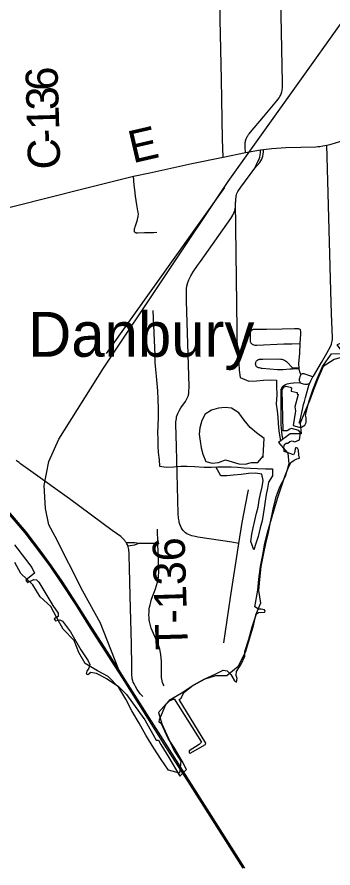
# Model space of a CAD drawing. Extents: x 63.4 to 97.4, y 0.4 to 22.4.
# Drawn here: x 69.147 to 69.704, y 14.543 to 16.043 of the extents above; entities that cross this region are included whole.
import ezdxf

# ---------------------------------------------------------------- set-up
doc = ezdxf.new("R2010")
doc.units = 0
for name, color, linetype in [('GM_X_County_Road', 7, 'Continuous'), ('GM_X_County_Road_Text', 7, 'Continuous'), ('GM_X_Major_Lake', 7, 'Continuous'), ('GM_X_Minor_River', 7, 'Continuous'), ('GM_X_Rail_Line', 7, 'Continuous'), ('GM_X_Township_Road', 7, 'Continuous'), ('GM_X_Township_Road_Text', 7, 'Continuous'), ('GM_X_Unincorporated_Text', 7, 'Continuous'), ('SH_Cut_Line', 7, 'Continuous')]:
    doc.layers.add(name, color=color, linetype=linetype)

msp = doc.modelspace()

# ---------------------------------------------------------------- linework, layer by layer
at = {"layer": 'GM_X_County_Road'}
for p, q in [((69.5103, 15.796), (69.5497, 15.8042)), ((69.5497, 15.8042), (69.5762, 15.8087))]:
    msp.add_line(p, q, dxfattribs=at)
for points in [[(69.6931, 15.8171), (69.701, 15.8189), (69.7158, 15.8236), (69.7305, 15.8292)], [(69.5762, 15.8087), (69.5773, 15.8089), (69.5814, 15.8094), (69.5959, 15.8112), (69.6208, 15.8125), (69.6737, 15.8141), (69.6773, 15.8144), (69.6806, 15.8148), (69.6859, 15.8155), (69.6931, 15.8171)], [(69.3521, 15.7622), (69.381, 15.7683), (69.4552, 15.7846), (69.5103, 15.796)], [(69.1254, 15.7052), (69.1419, 15.7092), (69.2655, 15.7405), (69.3521, 15.7622)], [(69.1423, 15.1125), (69.1618, 15.087), (69.1732, 15.0722), (69.1779, 15.0622), (69.1622, 15.0502), (69.1656, 15.0462), (69.1764, 15.051), (69.1813, 15.0506), (69.1856, 15.0467), (69.21, 15.0054), (69.2195, 14.9918), (69.2192, 14.9863), (69.2123, 14.9818), (69.2146, 14.9786), (69.2221, 14.9799), (69.2271, 14.9778), (69.2414, 14.9591), (69.2596, 14.9274), (69.2723, 14.908), (69.2755, 14.9014), (69.2734, 14.8949), (69.2699, 14.8896), (69.2689, 14.885), (69.2717, 14.8838), (69.2768, 14.8877), (69.2866, 14.8861), (69.3047, 14.8768), (69.3251, 14.8632), (69.34, 14.8484), (69.3503, 14.8341), (69.3721, 14.8041), (69.3921, 14.7678), (69.3965, 14.7681), (69.4005, 14.7603), (69.4148, 14.7376), (69.4341, 14.7044), (69.4456, 14.7166), (69.4378, 14.7308), (69.4239, 14.7549), (69.4132, 14.771), (69.4014, 14.7968), (69.3976, 14.7996), (69.3983, 14.8046), (69.4016, 14.8129), (69.4093, 14.8311), (69.4158, 14.8373), (69.4239, 14.8407), (69.4719, 14.7643), (69.4683, 14.7602), (69.4504, 14.749), (69.4504, 14.7461), (69.4523, 14.7452), (69.4793, 14.7607), (69.4798, 14.7626), (69.4327, 14.8395), (69.4361, 14.8419), (69.4413, 14.8522), (69.4576, 14.8649), (69.477, 14.8756), (69.4963, 14.8843), (69.5101, 14.8912), (69.5177, 14.8905), (69.5238, 14.8838), (69.5296, 14.8739), (69.5336, 14.8705), (69.535, 14.8769), (69.533, 14.8822), (69.5341, 14.8889), (69.5421, 14.9021), (69.5486, 14.916), (69.5487, 14.9242), (69.5555, 14.9459), (69.5616, 14.9676), (69.5694, 14.9907), (69.5726, 14.9933), (69.5833, 14.9935), (69.5844, 14.9949), (69.5833, 14.9978), (69.5776, 14.9992), (69.5726, 14.9988), (69.5664, 15.0031), (69.5714, 15.0322), (69.5733, 15.0516), (69.576, 15.0744), (69.5802, 15.0946), (69.584, 15.1151), (69.5885, 15.1341), (69.5998, 15.1721), (69.6064, 15.1938), (69.6189, 15.233), (69.625, 15.2478), (69.6298, 15.2576), (69.6356, 15.2614), (69.6402, 15.2639), (69.6452, 15.2654), (69.6439, 15.2707), (69.6432, 15.2793), (69.6417, 15.2825), (69.6384, 15.2841), (69.6374, 15.281), (69.6361, 15.2745), (69.6346, 15.271), (69.6296, 15.2727), (69.627, 15.2742), (69.618, 15.277), (69.6175, 15.2838), (69.6185, 15.2894), (69.6213, 15.2916), (69.6245, 15.2916), (69.6281, 15.2944), (69.6321, 15.2957), (69.6369, 15.2941), (69.6447, 15.2977), (69.6468, 15.3099), (69.6439, 15.3141), (69.6311, 15.3176), (69.6278, 15.3161), (69.6235, 15.3131), (69.616, 15.3131), (69.6144, 15.3849), (69.6167, 15.3905), (69.6215, 15.392), (69.6283, 15.3902), (69.6306, 15.3894), (69.6301, 15.3834), (69.6409, 15.3811), (69.6409, 15.3778), (69.6424, 15.3776), (69.6369, 15.3554), (69.6381, 15.3486), (69.6336, 15.3229), (69.6444, 15.3199), (69.6485, 15.3199), (69.6545, 15.3231), (69.6568, 15.3279), (69.6568, 15.3365), (69.6555, 15.341), (69.6618, 15.3664), (69.6686, 15.3858), (69.6762, 15.4048), (69.6857, 15.4269), (69.7016, 15.4492), (69.7182, 15.4497)]]:
    msp.add_lwpolyline(points, dxfattribs=at)
at = {"layer": 'GM_X_Major_Lake'}
for points in [[(69.7218, 15.4868), (69.7386, 15.4762), (69.7477, 15.4568), (69.7568, 15.4375), (69.7378, 15.4527), (69.7299, 15.4717), (69.7109, 15.4648), (69.7261, 15.4447), (69.7063, 15.4393), (69.6866, 15.4268), (69.6771, 15.4047), (69.6695, 15.3857), (69.6627, 15.3663), (69.654, 15.3458)], [(69.7219, 15.4863), (69.7386, 15.4762), (69.7477, 15.4568), (69.7568, 15.4375), (69.7378, 15.4527), (69.7299, 15.4717), (69.7109, 15.4648), (69.7261, 15.4447), (69.7063, 15.4393), (69.6866, 15.4268), (69.6771, 15.4047), (69.6695, 15.3857), (69.6627, 15.3663), (69.654, 15.3458)], [(69.654, 15.3458), (69.6464, 15.3268), (69.6479, 15.3078), (69.6285, 15.3082), (69.608, 15.293), (69.6244, 15.2739), (69.6263, 15.2549), (69.6198, 15.2329), (69.6096, 15.2139), (69.6027, 15.1949), (69.5978, 15.1755), (69.5936, 15.1553), (69.5895, 15.134), (69.5849, 15.115), (69.5811, 15.0945), (69.5769, 15.0743), (69.5743, 15.0515), (69.5724, 15.0321), (69.5762, 15.0093), (69.5675, 14.9884), (69.5625, 14.9675), (69.5564, 14.9458), (69.5496, 14.9242), (69.5367, 14.8979), (69.5166, 14.8812), (69.4969, 14.8816), (69.4779, 14.8755), (69.4585, 14.8648), (69.4361, 14.8504), (69.4149, 14.8378), (69.3963, 14.8169), (69.4024, 14.7968), (69.4141, 14.7709), (69.4236, 14.7504), (69.4358, 14.731), (69.4335, 14.7097), (69.4141, 14.715), (69.4012, 14.734), (69.3879, 14.7538), (69.3739, 14.7766), (69.3625, 14.7979), (69.3496, 14.8196), (69.3386, 14.8401), (69.3264, 14.861), (69.3075, 14.8804), (69.2885, 14.8903), (69.2672, 14.9032), (69.2558, 14.9226), (69.2475, 14.9435), (69.2281, 14.964), (69.2171, 14.9838), (69.2065, 15.0039), (69.1875, 15.0207), (69.1746, 15.042), (69.1537, 15.0621), (69.1431, 15.0815)]]:
    msp.add_lwpolyline(points, dxfattribs=at)
at = {"layer": 'GM_X_Minor_River'}
for points in [[(69.5126, 15.7425), (69.3041, 15.4496)], [(69.5317, 15.7171), (69.5353, 15.4461)], [(69.3861, 15.5252), (69.3896, 15.4466)], [(69.3894, 15.4509), (69.3899, 15.434), (69.3908, 15.4214), (69.392, 15.4096), (69.3936, 15.397), (69.3945, 15.3841), (69.3949, 15.3685), (69.3957, 15.3529), (69.3958, 15.3384), (69.3954, 15.3213), (69.3948, 15.3103), (69.3949, 15.2989), (69.395, 15.2867), (69.3959, 15.2753), (69.3975, 15.2623), (69.398, 15.2513), (69.4105, 15.2495), (69.4231, 15.2499), (69.4357, 15.2508), (69.4467, 15.2509), (69.4596, 15.2503), (69.4771, 15.2495), (69.4893, 15.2492), (69.5007, 15.2497), (69.5121, 15.2499), (69.5243, 15.2496), (69.5357, 15.249), (69.5467, 15.2483), (69.5585, 15.2477), (69.571, 15.247), (69.5851, 15.2463), (69.5973, 15.2461), (69.5974, 15.2339), (69.5903, 15.223), (69.5885, 15.212), (69.5864, 15.201), (69.5846, 15.1893), (69.5828, 15.1768), (69.5807, 15.1658), (69.5789, 15.1548), (69.5756, 15.1423), (69.5718, 15.1272), (69.5681, 15.1147), (69.5644, 15.1038), (69.5591, 15.1184), (69.5612, 15.1309), (69.5634, 15.1426), (69.566, 15.1551), (69.5693, 15.168), (69.5718, 15.1789), (69.574, 15.1914), (69.5761, 15.2024), (69.5791, 15.2149), (69.5808, 15.2259), (69.5784, 15.237), (69.5671, 15.2388), (69.5549, 15.2383), (69.5419, 15.2366), (69.5285, 15.235), (69.5171, 15.2338), (69.5061, 15.234), (69.4976, 15.2496)], [(69.5353, 15.4482), (69.5379, 15.433), (69.5387, 15.4201), (69.5404, 15.4075), (69.5558, 15.401), (69.5691, 15.4015), (69.5817, 15.4024), (69.5935, 15.4032), (69.6046, 15.4026), (69.6043, 15.3912), (69.6048, 15.3775), (69.604, 15.3604), (69.6053, 15.3486), (69.6065, 15.3375), (69.6074, 15.3261), (69.6087, 15.3135), (69.6113, 15.2954)], [(69.5828, 15.2996), (69.569, 15.3098), (69.5578, 15.3192), (69.5471, 15.332), (69.5382, 15.3451), (69.5251, 15.3534), (69.5137, 15.3544), (69.5019, 15.3532), (69.49, 15.35), (69.4788, 15.343), (69.4729, 15.3318), (69.4691, 15.3185), (69.4681, 15.3075), (69.4698, 15.2953)], [(69.5828, 15.2996), (69.569, 15.3098), (69.5578, 15.3192), (69.5471, 15.332), (69.5382, 15.3451), (69.5251, 15.3534), (69.5137, 15.3544), (69.5019, 15.3532), (69.49, 15.35), (69.4788, 15.343), (69.4729, 15.3318), (69.4691, 15.3185), (69.4681, 15.3075), (69.4698, 15.2953), (69.4714, 15.2835), (69.4746, 15.272), (69.4796, 15.2593), (69.491, 15.2564), (69.5024, 15.2573), (69.5147, 15.262), (69.5264, 15.2587), (69.5377, 15.2554), (69.5491, 15.2544), (69.5602, 15.2575), (69.5717, 15.2577), (69.581, 15.2685), (69.5817, 15.2795), (69.5828, 15.2996)], [(69.4698, 15.2953), (69.4714, 15.2835), (69.4746, 15.272), (69.4796, 15.2593), (69.491, 15.2564), (69.5024, 15.2573), (69.5147, 15.262), (69.5264, 15.2587), (69.5377, 15.2554), (69.5491, 15.2544), (69.5602, 15.2575), (69.5717, 15.2577), (69.581, 15.2685), (69.5817, 15.2795), (69.5828, 15.2996)], [(69.581, 15.2666), (69.581, 15.2693)]]:
    msp.add_lwpolyline(points, dxfattribs=at)
at = {"layer": 'GM_X_Rail_Line'}
for points in [[(69.3319, 14.8787), (69.2942, 14.9743), (69.2629, 15.0308), (69.214, 15.1273), (69.2031, 15.1476), (69.1971, 15.1765), (69.195, 15.2169), (69.2031, 15.259), (69.2208, 15.2984), (69.2996, 15.424), (69.5191, 15.7529), (69.8464, 16.212), (70.0807, 16.5521), (70.1469, 16.6295), (70.1923, 16.6638), (70.2325, 16.6879), (70.3054, 16.7158), (70.3574, 16.7343), (70.4785, 16.7566), (71.288, 16.7798)], [(69.1259, 15.1743), (69.1605, 15.1336), (69.1884, 15.0972), (69.2052, 15.074), (69.2238, 15.0469), (69.2498, 15.007), (69.2761, 14.9653), (69.3195, 14.8978), (69.3322, 14.8781), (69.406, 14.7612), (69.4522, 14.689), (69.5452, 14.5427)], [(69.1276, 15.1758), (69.1623, 15.135), (69.1902, 15.0986), (69.2071, 15.0753), (69.2257, 15.0482), (69.2517, 15.0082), (69.278, 14.9665), (69.3215, 14.8991), (69.3341, 14.8793), (69.408, 14.7625), (69.4542, 14.6902), (69.548, 14.5427)]]:
    msp.add_lwpolyline(points, dxfattribs=at)
at = {"layer": 'GM_X_Township_Road'}
for p, q in [((69.6446, 15.4224), (69.6443, 15.4242)), ((69.3954, 15.1156), (69.3947, 15.1397)), ((69.3616, 15.1151), (69.3954, 15.1156))]:
    msp.add_line(p, q, dxfattribs=at)
for points in [[(69.5103, 15.796), (69.5093, 15.8276), (69.5074, 15.9329), (69.5053, 16.0382), (69.5042, 16.1002), (69.5037, 16.128), (69.5026, 16.19), (69.5026, 16.1931)], [(69.5497, 15.8042), (69.5493, 15.8133), (69.5493, 15.8187), (69.5494, 15.8213), (69.5495, 15.8233), (69.5498, 15.8248), (69.5502, 15.8265), (69.5507, 15.8278), (69.5514, 15.8295), (69.5519, 15.8306), (69.5529, 15.8321), (69.5538, 15.8334), (69.5553, 15.8356), (69.5562, 15.8369), (69.5587, 15.8399), (69.5812, 15.8667), (69.6051, 15.895), (69.6073, 15.8978), (69.609, 15.9003), (69.6103, 15.9025), (69.6113, 15.9042), (69.6119, 15.9056), (69.6126, 15.9072), (69.6134, 15.9092), (69.6138, 15.9109), (69.6142, 15.9131), (69.6144, 15.9147), (69.6147, 15.9177), (69.6149, 15.9214), (69.615, 15.927), (69.6112, 16.1068)], [(69.6687, 15.4085), (69.6694, 15.4098), (69.6835, 15.434), (69.6931, 15.4502), (69.6995, 15.462), (69.7012, 15.466), (69.7022, 15.4691), (69.7027, 15.4715), (69.7031, 15.4741), (69.7032, 15.4775), (69.7025, 15.4917), (69.7013, 15.5197), (69.7, 15.5602), (69.6945, 15.7753), (69.6931, 15.8171)], [(69.5661, 15.7762), (69.5706, 15.7808), (69.5748, 15.7862), (69.5769, 15.7892), (69.5783, 15.792), (69.5794, 15.7942), (69.5804, 15.7973), (69.5809, 15.8009), (69.5813, 15.8053), (69.5814, 15.8094)], [(69.5661, 15.7762), (69.5715, 15.7883), (69.5737, 15.7924), (69.5752, 15.7955), (69.5758, 15.7994), (69.5762, 15.8041), (69.5762, 15.8087)], [(69.5382, 15.115), (69.5259, 15.117), (69.4657, 15.126), (69.4611, 15.1268), (69.4553, 15.1282), (69.4494, 15.1304), (69.4461, 15.132), (69.4442, 15.1336), (69.4397, 15.1378), (69.438, 15.1402), (69.4361, 15.1429), (69.4337, 15.1486), (69.433, 15.1515), (69.4325, 15.1547), (69.4318, 15.1593), (69.4313, 15.1678), (69.4283, 15.2853), (69.427, 15.3258), (69.4271, 15.3293), (69.4273, 15.3322), (69.4278, 15.335), (69.4283, 15.338), (69.4293, 15.341), (69.4304, 15.3441), (69.432, 15.3475), (69.4331, 15.3495), (69.436, 15.3538), (69.4437, 15.365), (69.4458, 15.3685), (69.448, 15.373), (69.449, 15.3757), (69.4494, 15.3774), (69.4496, 15.379), (69.4499, 15.382), (69.4504, 15.3913), (69.446, 15.5422), (69.4457, 15.5593), (69.4459, 15.5642), (69.4465, 15.5686), (69.4478, 15.5746), (69.4498, 15.5795), (69.4515, 15.5828), (69.4532, 15.5864), (69.4577, 15.5937), (69.4654, 15.6048), (69.4702, 15.6117), (69.5241, 15.6879), (69.5274, 15.6932), (69.53, 15.6988), (69.531, 15.7019), (69.5317, 15.7048), (69.5321, 15.7081), (69.5324, 15.7109), (69.5328, 15.7203), (69.5329, 15.7225), (69.5331, 15.7252), (69.5334, 15.7274), (69.534, 15.7294), (69.5347, 15.7315), (69.5364, 15.7351), (69.5413, 15.743), (69.5661, 15.7762)], [(69.3935, 15.6629), (69.3873, 15.6626), (69.3716, 15.6623), (69.3591, 15.6618), (69.3577, 15.6619), (69.3569, 15.6621), (69.3562, 15.6623), (69.3556, 15.6626), (69.3549, 15.6634), (69.3543, 15.6642), (69.354, 15.6653), (69.3538, 15.6661), (69.3539, 15.6668), (69.3541, 15.6686), (69.3543, 15.6697), (69.3546, 15.6706), (69.3553, 15.6728), (69.3594, 15.6855), (69.3602, 15.6891), (69.3605, 15.6902), (69.3606, 15.6916), (69.3609, 15.6955), (69.3607, 15.6986), (69.3602, 15.7013), (69.3596, 15.7046), (69.3583, 15.7116), (69.3558, 15.7272), (69.3545, 15.7384), (69.3535, 15.7462), (69.3521, 15.7622)], [(69.6464, 15.4673), (69.6473, 15.4844), (69.6473, 15.4866), (69.6473, 15.4881), (69.6472, 15.4889), (69.647, 15.4902), (69.6465, 15.4911), (69.646, 15.4917), (69.6451, 15.4924), (69.6441, 15.4928), (69.6431, 15.493), (69.6419, 15.4932), (69.6404, 15.4933), (69.636, 15.4933), (69.6146, 15.4925), (69.5866, 15.4922), (69.5705, 15.492), (69.5671, 15.492), (69.5656, 15.492), (69.5648, 15.492), (69.563, 15.4917), (69.5623, 15.4914), (69.5615, 15.491), (69.5607, 15.4905), (69.56, 15.4899), (69.5594, 15.4892), (69.5588, 15.4882), (69.5584, 15.4873), (69.5582, 15.4867), (69.5579, 15.4851), (69.5578, 15.4833), (69.5578, 15.4815), (69.5577, 15.4789), (69.5578, 15.473), (69.5582, 15.4705), (69.5585, 15.4695), (69.5589, 15.4685), (69.5594, 15.4678), (69.5601, 15.467), (69.5609, 15.4664), (69.5617, 15.4659), (69.5628, 15.4653), (69.5646, 15.4648), (69.5662, 15.4646), (69.5681, 15.4645), (69.5695, 15.4645), (69.6175, 15.4665), (69.6314, 15.4669), (69.6464, 15.4673)], [(69.6443, 15.4242), (69.6441, 15.4264), (69.644, 15.429), (69.644, 15.4324), (69.6444, 15.4379), (69.6456, 15.4501), (69.6464, 15.4673)], [(69.6446, 15.4224), (69.6325, 15.4222), (69.6278, 15.4222), (69.6154, 15.421), (69.6061, 15.421), (69.5794, 15.4231), (69.5778, 15.4232), (69.5759, 15.4236), (69.5742, 15.4241), (69.5727, 15.4246), (69.5714, 15.4252), (69.5705, 15.4258), (69.5695, 15.4266), (69.5688, 15.4275), (69.5681, 15.4285), (69.5677, 15.4297), (69.5675, 15.431), (69.5676, 15.4319), (69.5677, 15.4329), (69.5679, 15.4339), (69.5682, 15.4346), (69.5685, 15.4353), (69.5692, 15.4365), (69.5698, 15.4371), (69.5704, 15.4376), (69.5716, 15.4384), (69.5728, 15.4389), (69.5738, 15.4392), (69.5745, 15.4394), (69.576, 15.4397), (69.5772, 15.4398), (69.5785, 15.4399), (69.5803, 15.4399), (69.6084, 15.44), (69.6119, 15.4397), (69.6139, 15.4394), (69.6153, 15.4392), (69.6168, 15.4386), (69.6186, 15.438), (69.6205, 15.4369), (69.6222, 15.4355), (69.6243, 15.4334), (69.6308, 15.4259), (69.6315, 15.4253), (69.6323, 15.4248), (69.6334, 15.4246), (69.6347, 15.4244), (69.6359, 15.4244), (69.6396, 15.4243), (69.6443, 15.4242)], [(69.6473, 15.4124), (69.6458, 15.4174), (69.6446, 15.4224)], [(69.6473, 15.4124), (69.6466, 15.4112), (69.6457, 15.4087), (69.6449, 15.4061), (69.6444, 15.4045), (69.6444, 15.403), (69.6445, 15.4018), (69.6449, 15.4006), (69.6454, 15.3995), (69.6464, 15.3985), (69.648, 15.3973), (69.6495, 15.3967), (69.6514, 15.3962), (69.6544, 15.3956), (69.6568, 15.3954), (69.6577, 15.3954), (69.6589, 15.3956), (69.66, 15.3959), (69.661, 15.3963), (69.6619, 15.397), (69.6629, 15.3978)], [(69.6687, 15.4085), (69.6649, 15.4098), (69.6598, 15.4117), (69.6566, 15.4129), (69.6544, 15.4135), (69.6529, 15.4138), (69.6512, 15.4138), (69.6496, 15.4136), (69.6483, 15.4132), (69.6473, 15.4124)], [(69.6629, 15.3978), (69.6635, 15.3986), (69.6651, 15.4016), (69.6687, 15.4085)], [(69.6153, 15.3), (69.6146, 15.3054), (69.6131, 15.3186), (69.6128, 15.3235), (69.6128, 15.3324), (69.6124, 15.3797), (69.6129, 15.3859), (69.6137, 15.3889), (69.6152, 15.3915), (69.6175, 15.3935), (69.6202, 15.395), (69.623, 15.3959), (69.6288, 15.3971), (69.6349, 15.3978), (69.6464, 15.3985)], [(69.6446, 15.3266), (69.6459, 15.3323), (69.6503, 15.3507), (69.6523, 15.3596), (69.6536, 15.3651), (69.6553, 15.3721), (69.6585, 15.3825), (69.6603, 15.3891), (69.6617, 15.3935), (69.6629, 15.3978)], [(69.342, 15.1109), (69.3416, 15.1121), (69.3406, 15.1144), (69.3394, 15.1162), (69.3384, 15.1179), (69.337, 15.1199), (69.3345, 15.1226), (69.3298, 15.1268), (69.3146, 15.1378), (69.2396, 15.1933), (69.1714, 15.2422), (69.1533, 15.2552), (69.1504, 15.2573), (69.1478, 15.2594), (69.1454, 15.2618)], [(69.5382, 15.115), (69.5438, 15.1516), (69.554, 15.2034), (69.5553, 15.2094)], [(69.3394, 15.1162), (69.3549, 15.1167), (69.3616, 15.1151)], [(69.342, 15.1109), (69.3549, 15.1125), (69.3616, 15.1151)], [(69.369, 14.8452), (69.3662, 14.8474), (69.3641, 14.8495), (69.3616, 14.8532), (69.359, 14.8571), (69.3558, 14.8624), (69.3534, 14.8671), (69.3517, 14.8702), (69.3508, 14.8728), (69.3503, 14.8745), (69.3501, 14.8759), (69.3497, 14.8789), (69.3495, 14.882), (69.3493, 14.8975), (69.3487, 14.938), (69.3465, 15.0219), (69.3455, 15.0717), (69.3447, 15.0927), (69.3446, 15.0965), (69.3445, 15.0987), (69.3442, 15.1019), (69.3439, 15.1044), (69.3435, 15.1063), (69.3427, 15.1089), (69.342, 15.1109)], [(69.4061, 14.8641), (69.4046, 14.8668), (69.4034, 14.8697), (69.4026, 14.8727), (69.4019, 14.8788), (69.4014, 14.9068), (69.4005, 14.9192), (69.3986, 14.9282), (69.3957, 14.9371), (69.3837, 14.9657), (69.3823, 14.9704), (69.3811, 14.9746), (69.3805, 14.9772), (69.3801, 14.9802), (69.3798, 14.9839), (69.3794, 14.9895), (69.3796, 14.9932), (69.38, 14.9993), (69.3805, 15.0024), (69.3815, 15.0069), (69.3826, 15.0115), (69.3842, 15.0166), (69.3909, 15.0349), (69.3946, 15.0468), (69.3956, 15.051), (69.3963, 15.0559), (69.3968, 15.0652), (69.3954, 15.1156)], [(69.5116, 14.9398), (69.5235, 15.0196), (69.5382, 15.115)]]:
    msp.add_lwpolyline(points, dxfattribs=at)
at = {"layer": 'SH_Cut_Line'}
msp.add_lwpolyline([(69.1423, 15.1125), (69.1618, 15.087), (69.1732, 15.0722), (69.1779, 15.0622), (69.1622, 15.0502), (69.1656, 15.0462), (69.1764, 15.051), (69.1813, 15.0506), (69.1856, 15.0467), (69.21, 15.0054), (69.2195, 14.9918), (69.2192, 14.9863), (69.2123, 14.9818), (69.2146, 14.9786), (69.2221, 14.9799), (69.2271, 14.9778), (69.2414, 14.9591), (69.2596, 14.9274), (69.2723, 14.908), (69.2755, 14.9014), (69.2734, 14.8949), (69.2699, 14.8896), (69.2689, 14.885), (69.2717, 14.8838), (69.2768, 14.8877), (69.2866, 14.8861), (69.3047, 14.8768), (69.3251, 14.8632), (69.34, 14.8484), (69.3503, 14.8341), (69.3721, 14.8041), (69.3921, 14.7678), (69.3965, 14.7681), (69.4005, 14.7603), (69.4148, 14.7376), (69.4341, 14.7044), (69.4456, 14.7166), (69.4378, 14.7308), (69.4239, 14.7549), (69.4132, 14.771), (69.4014, 14.7968), (69.3976, 14.7996), (69.3983, 14.8046), (69.4016, 14.8129), (69.4093, 14.8311), (69.4158, 14.8373), (69.4239, 14.8407), (69.4719, 14.7643), (69.4683, 14.7602), (69.4504, 14.749), (69.4504, 14.7461), (69.4523, 14.7452), (69.4793, 14.7607), (69.4798, 14.7626), (69.4327, 14.8395), (69.4361, 14.8419), (69.4413, 14.8522), (69.4576, 14.8649), (69.477, 14.8756), (69.4963, 14.8843), (69.5101, 14.8912), (69.5177, 14.8905), (69.5238, 14.8838), (69.5296, 14.8739), (69.5336, 14.8705), (69.535, 14.8769), (69.533, 14.8822), (69.5341, 14.8889), (69.5421, 14.9021), (69.5486, 14.916), (69.5487, 14.9242), (69.5555, 14.9459), (69.5616, 14.9676), (69.5694, 14.9907), (69.5726, 14.9933), (69.5833, 14.9935), (69.5844, 14.9949), (69.5833, 14.9978), (69.5776, 14.9992), (69.5726, 14.9988), (69.5664, 15.0031), (69.5714, 15.0322), (69.5733, 15.0516), (69.576, 15.0744), (69.5802, 15.0946), (69.584, 15.1151), (69.5885, 15.1341), (69.5998, 15.1721), (69.6064, 15.1938), (69.6189, 15.233), (69.625, 15.2478), (69.6298, 15.2576), (69.6356, 15.2614), (69.6402, 15.2639), (69.6452, 15.2654), (69.6439, 15.2707), (69.6432, 15.2793), (69.6417, 15.2825), (69.6384, 15.2841), (69.6374, 15.281), (69.6361, 15.2745), (69.6346, 15.271), (69.6296, 15.2727), (69.627, 15.2742), (69.618, 15.277), (69.6175, 15.2838), (69.6185, 15.2894), (69.6213, 15.2916), (69.6245, 15.2916), (69.6281, 15.2944), (69.6321, 15.2957), (69.6369, 15.2941), (69.6447, 15.2977), (69.6468, 15.3099), (69.6439, 15.3141), (69.6311, 15.3176), (69.6278, 15.3161), (69.6235, 15.3131), (69.616, 15.3131), (69.6144, 15.3849), (69.6167, 15.3905), (69.6215, 15.392), (69.6283, 15.3902), (69.6306, 15.3894), (69.6301, 15.3834), (69.6409, 15.3811), (69.6409, 15.3778), (69.6424, 15.3776), (69.6369, 15.3554), (69.6381, 15.3486), (69.6336, 15.3229), (69.6444, 15.3199), (69.6485, 15.3199), (69.6545, 15.3231), (69.6568, 15.3279), (69.6568, 15.3365), (69.6555, 15.341), (69.6618, 15.3664), (69.6686, 15.3858), (69.6762, 15.4048), (69.6857, 15.4269), (69.7016, 15.4492), (69.7182, 15.4497)], dxfattribs=at)

# ---------------------------------------------------------------- texts
at = {"layer": 'GM_X_County_Road_Text'}
for s, rotation, p in [('6', 91.6237, (69.2195, 15.9138)), ('3', 91.6161, (69.2205, 15.8791)), ('1', 91.5947, (69.2215, 15.8444)), ('-', 91.5593, (69.2221, 15.8212)), ('E', 13.0063, (69.3509, 15.7848)), ('C', 91.4928, (69.2233, 15.7748))]:
    msp.add_text(s, height=0.0568, rotation=rotation, dxfattribs=at).set_placement(p)
at = {"layer": 'GM_X_Township_Road_Text'}
msp.add_text('T-136', height=0.05682, rotation=91.673, dxfattribs=at).set_placement((69.4482, 14.9279))
at = {"layer": 'GM_X_Unincorporated_Text'}
msp.add_text('Danbury', height=0.07898, rotation=0, dxfattribs=at).set_placement((69.1663, 15.444))

doc.saveas('drawing.dxf')
